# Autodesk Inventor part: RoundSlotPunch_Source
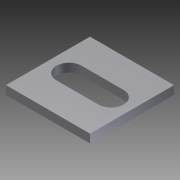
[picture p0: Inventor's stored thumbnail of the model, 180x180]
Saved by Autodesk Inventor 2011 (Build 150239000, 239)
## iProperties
Created: 2007-02
Part Number: RoundSlotPunch_Source
Material: Default
Document SubType Name: Sheet Metal
Designer: Autodesk, Inc.
Mass: 0.077931 g
Surface Area: 2.15288 cm^2
Volume: 0.077931 cm^3
Density: 1 g/cm^3
Sheet Metal Rule: 1 mm
Author: Autodesk, Inc.
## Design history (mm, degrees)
node "Face1"
  sketch "Sketch1"
    geometry: L1 (-5, 5)-(5, 5); L2 (5, 5)-(5, -5); L3 (5, -5)-(-5, -5); L4 (-5, -5)-(-5, 5); L5 (-5, 5)-(5, -5); 2 further points
    constraints: 10 end point, 2 parallel, 1 coincident, 1 horizontal, 1 midpoint, 1 perpendicular
    dimensions: "d0" = 10 distance of L2.end L3.end; "d1" = 10 distance of L1.end L2.end (= d0)
sketch "Sketch2"
  geometry: L1 (-2.5, 1.5)-(2.5, 1.5); L2 (-2.5, -1.5)-(2.5, -1.5); L3 (-2.5, 0)-(2.5, 0); L4 (2.5, 0)-(1.658, 0); A1 r 1.5 centre (-2.5, 0) between (-2.5, 1.5) and (-2.5, -1.5); A2 r 1.5 centre (2.5, 0) between (2.5, -1.5) and (2.5, 1.5); 2 further points
  constraints: 8 end point, 4 point on circle, 3 tangent, 2 centre point, 2 parallel, 1 coincident, 1 horizontal, 1 point on line
  dimensions: "d11" = 5 distance of L3.start L3.end; "d12" = 3 distance between parallel lines of L2 L1
cut "Cut1" sketch "Sketch2" dims "d3" = 1 (= Thickness), "d4" = 0
body "Solid1"
face "Plate1" dims "Thickness" = 1
other parameters: "BendRadius" = 0.5, "BendReliefWidth" = 1 (= Thickness), "BendReliefDepth" = 0.5 (= 0.5 x Thickness), "CornerReliefSize" = 4 (= 4 x Thickness), "SeamGap" = 0.01, "MinimumRemnant" = 2 (= 2 x Thickness), "TransitionRadius" = 0.5 (= BendRadius), "JacobiRadiusSize" = 1 (= Thickness), "d2" = 0.5 (= BendRadius), "GapSize" = 1 (= Thickness)
